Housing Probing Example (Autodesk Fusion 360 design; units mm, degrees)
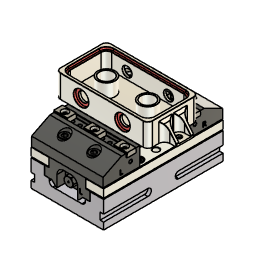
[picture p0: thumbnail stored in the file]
parameter "stockX" = 165.1 comment "Stock in X"
parameter "stockY" = 76.2 comment "Stock in Y"
parameter "stockZ" = 38.1 comment "Stock in Z"
as_built_joint "As-built1"
sketch "Sketch1" plane through (0, 0, 0) normal (0, 0, 1) x axis (1, 0, 0)
  line L1 (-63.5, 34.925) -> (63.5, 34.925)
  line L2 (-63.5, -34.925) -> (-63.5, 34.925)
  line L3 (63.5, -34.925) -> (-63.5, -34.925)
  line L4 (63.5, 34.925) -> (63.5, -34.925)
  line L5 (-63.5, -34.925) -> (63.5, 34.925)
  line L6 (63.5, -34.925) -> (-63.5, 34.925)
  point P6 (0, 0)
  point P1 (0, 0)
  point P2 (63.5, 34.925)
  point P5 (63.5, -34.925)
  point P3 (-63.5, 34.925)
  perpendicular L1 L2
  parallel L1 L3
  parallel L2 L4
  horizontal L1
  coincident L5 P6
  coincident L6 P6
  coincident P1 P6
  dimension "d1" distance P2 P5 = 69.85
  dimension "d2" distance P2 P3 = 127
extrude "Extrude1" new body sketch "Sketch1" profile of L1 L2 L3 L4 along normal blind 31.75
sketch "Sketch2" plane through (0, 0, 31.75) normal (0, 0, 1) x axis (-1, 0, 0)
  line L1 (-63.5, -34.925) -> (-63.5, 34.925)
  line L2 (63.5, -34.925) -> (-63.5, -34.925)
  line L3 (63.5, 34.925) -> (63.5, -34.925)
  line L4 (-63.5, 34.925) -> (63.5, 34.925)
  line L5 (-57.15, 28.575) -> (57.15, 28.575)
  line L6 (-57.15, -28.575) -> (-57.15, 28.575)
  line L7 (57.15, -28.575) -> (-57.15, -28.575)
  line L8 (57.15, 28.575) -> (57.15, -28.575)
  dimension "d5" = 6.35
extrude "Extrude2" cut sketch "Sketch2" profile of L8 L5 L6 L7 against normal blind 25.4 (magnitude of "-1.2500 in + 0.25 in")
fillet "Fillet1" radius 7.3025 (= "( 0.25 * 1.15 ) * 1 in")
sketch "Sketch3" plane through (0, 0, 6.35) normal (0, 0, 1) x axis (-1, 0, 0)
  line L1 (-57.15, -21.2725) -> (-57.15, 21.2725)
  line L2 (49.8475, -28.575) -> (-49.8475, -28.575)
  line L3 (57.15, 21.2725) -> (57.15, -21.2725)
  line L4 (-49.8475, 28.575) -> (49.8475, 28.575)
  line L5 (-57.15, 0) -> (57.15, 0)
  line L6 (-57.15, 21.2725) -> (-57.15, -21.2725)
  arc A1 centre (-49.8475, 21.2725) radius 7.3025 clockwise from (-57.15, 21.2725) to (-49.8475, 28.575)
  arc A2 centre (-49.8475, -21.2725) radius 7.3025 clockwise from (-49.8475, -28.575) to (-57.15, -21.2725)
  arc A3 centre (49.8475, -21.2725) radius 7.3025 clockwise from (57.15, -21.2725) to (49.8475, -28.575)
  arc A4 centre (49.8475, 21.2725) radius 7.3025 clockwise from (49.8475, 28.575) to (57.15, 21.2725)
  circle C1 centre (-28.575, 0) radius 9.525
  circle C2 centre (28.575, 0) radius 9.525
  circle C3 centre (28.575, 0) radius 12.065
  circle C4 centre (-28.575, 0) radius 12.065
  point P14 (57.15, 0)
  point P15 (-57.15, 0)
  point P16 (-28.575, 0)
  point P17 (28.575, 0)
  point P1 (0, 0)
  midpoint L3 P14
  midpoint L1 P15
  coincident L5 P16
  coincident L5 P17
  equal C1 C2
  dimension "d9" distance P1 L6 = 57.15
  dimension "d10" distance P1 P16 = 28.575 (= "2.2500 in / 2")
  dimension "d11" distance P1 P17 = 28.575 (= "d10")
  dimension "d12" diameter C1 = 19.05
  dimension "d13" = 2.54
  dimension "d14" = 2.54 (= "d13")
extrude "Extrude3" add sketch "Sketch3" profile of C1 C2 C4 C3 along normal blind 19.05 (= "1.0000 in - 0.25 in")
sketch "Sketch4" plane through (0, 0, 6.35) normal (0, 0, 1) x axis (-1, 0, 0)
  circle C1 centre (28.575, 0) radius 6.6675
  circle C2 centre (-28.575, 0) radius 6.6675
  circle C3 centre (-28.575, 0) radius 9.525
  circle C4 centre (28.575, 0) radius 9.525
  concentric C2 C3
  concentric C1 C4
  equal C1 C2
  dimension "d17" diameter C1 = 13.335
extrude "Extrude4" cut sketch "Sketch4" profile of C1 C2 no distance stored
sketch "Sketch5" plane through (0, 0, 0) normal (0, 0, -1) x axis (1, 0, 0)
  circle C1 centre (-28.575, 0) radius 10.16
  circle C2 centre (28.575, 0) radius 10.16
  circle C3 centre (28.575, 0) radius 6.6675
  circle C4 centre (-28.575, 0) radius 6.6675
  concentric C2 C3
  concentric C1 C4
  equal C1 C2
  dimension "d19" diameter C2 = 20.32
extrude "Extrude5" cut sketch "Sketch5" against normal blind 3.175 (magnitude of "-0.2500 in / 2")
fillet "Fillet2" radius 6.35
sketch "Sketch6" plane through (0, 0, 31.75) normal (0, 0, 1) x axis (-1, 0, 0)
  line L1 (-63.5, -28.575) -> (-63.5, 28.575)
  line L2 (57.15, -34.925) -> (-57.15, -34.925)
  line L3 (63.5, 28.575) -> (63.5, -28.575)
  line L4 (-57.15, 34.925) -> (57.15, 34.925)
  line L5 (49.8475, 28.575) -> (-49.8475, 28.575)
  line L6 (57.15, -21.2725) -> (57.15, 21.2725)
  line L7 (-49.8475, -28.575) -> (49.8475, -28.575)
  line L8 (-57.15, 21.2725) -> (-57.15, -21.2725)
  line L9 (-49.8475, -31.115) -> (49.8475, -31.115)
  line L10 (59.69, -21.2725) -> (59.69, 21.2725)
  line L11 (49.8475, 31.115) -> (-49.8475, 31.115)
  line L12 (-59.69, 21.2725) -> (-59.69, -21.2725)
  arc A1 centre (-57.15, 28.575) radius 6.35 clockwise from (-63.5, 28.575) to (-57.15, 34.925)
  arc A2 centre (-57.15, -28.575) radius 6.35 clockwise from (-57.15, -34.925) to (-63.5, -28.575)
  arc A3 centre (57.15, -28.575) radius 6.35 clockwise from (63.5, -28.575) to (57.15, -34.925)
  arc A4 centre (57.15, 28.575) radius 6.35 clockwise from (57.15, 34.925) to (63.5, 28.575)
  arc A5 centre (49.8475, 21.2725) radius 7.3025 clockwise from (49.8475, 28.575) to (57.15, 21.2725)
  arc A6 centre (49.8475, -21.2725) radius 7.3025 clockwise from (57.15, -21.2725) to (49.8475, -28.575)
  arc A7 centre (-49.8475, -21.2725) radius 7.3025 clockwise from (-49.8475, -28.575) to (-57.15, -21.2725)
  arc A8 centre (-49.8475, 21.2725) radius 7.3025 clockwise from (-57.15, 21.2725) to (-49.8475, 28.575)
  arc A9 centre (-49.8475, -21.2725) radius 9.8425 clockwise from (-49.8475, -31.115) to (-59.69, -21.2725)
  arc A10 centre (49.8475, -21.2725) radius 9.8425 clockwise from (59.69, -21.2725) to (49.8475, -31.115)
  arc A11 centre (49.8475, 21.2725) radius 9.8425 clockwise from (49.8475, 31.115) to (59.69, 21.2725)
  arc A12 centre (-49.8475, 21.2725) radius 9.8425 clockwise from (-59.69, 21.2725) to (-49.8475, 31.115)
  dimension "d23" = 2.54
extrude "Extrude6" cut sketch "Sketch6" profile of L5 A5 L6 A6 L7 A7 L8 A8 L12 A9 L9 A10 L10 A11 L11 A12 against normal blind 3.175
sketch "Sketch7" plane through (0, -34.925, 0) normal (0, -1, 0) x axis (1, 0, 0)
  line L1 (-40.64, 25.4) -> (-16.51, 25.4)
  line L2 (-16.51, 6.35) -> (-40.64, 6.35)
  line L3 (16.51, 25.4) -> (40.64, 25.4)
  line L4 (40.64, 6.35) -> (16.51, 6.35)
  line L5 (-28.575, 6.35) -> (-28.575, 25.4)
  line L6 (28.575, 6.35) -> (28.575, 25.4)
  circle C1 centre (-28.575, 15.875) radius 6.6675
  circle C2 centre (28.575, 15.875) radius 6.6675
  point P10 (-28.575, 25.4)
  point P11 (-28.575, 6.35)
  point P12 (28.575, 25.4)
  point P13 (28.575, 6.35)
  point P14 (-28.575, 15.875)
  point P15 (28.575, 15.875)
  midpoint L1 P10
  midpoint L2 P11
  midpoint L3 P12
  midpoint L4 P13
  midpoint L5 P14
  midpoint L6 P15
  equal C1 C2
  dimension "d26" diameter C2 = 13.335
extrude "Extrude7" cut sketch "Sketch7" profile of C1 C2 against normal blind 6.35
sketch "Sketch8" plane through (0, 34.925, 0) normal (0, 1, 0) x axis (-1, 0, 0)
  circle C1 centre (28.575, 15.875) radius 6.6675
  circle C2 centre (28.575, 15.875) radius 6.6675
  circle C3 centre (-28.575, 15.875) radius 6.6675
  circle C4 centre (-28.575, 15.875) radius 6.6675
extrude "Extrude8" cut sketch "Sketch8" against normal blind 6.35
sketch "Sketch9" plane through (0, -34.925, 0) normal (0, -1, 0) x axis (1, 0, 0)
  circle C1 centre (28.575, 15.875) radius 10.4775
  circle C2 centre (-28.575, 15.875) radius 10.4775
  circle C3 centre (28.575, 15.875) radius 6.6675
  circle C4 centre (-28.575, 15.875) radius 6.6675
  concentric C1 C3
  concentric C2 C4
  equal C1 C2
  dimension "d31" distance C1 C3 = 3.81
extrude "Extrude9" cut sketch "Sketch9" against normal blind 3.175 (magnitude of "-0.2500 in / 2")
sketch "Sketch10" plane through (0, 34.925, 0) normal (0, 1, 0) x axis (-1, 0, 0)
  circle C1 centre (28.575, 15.875) radius 6.6675
  circle C2 centre (28.575, 15.875) radius 10.4775
  circle C3 centre (-28.575, 15.875) radius 6.6675
  circle C4 centre (-28.575, 15.875) radius 10.4775
extrude "Extrude10" cut sketch "Sketch10" against normal blind 3.175 (magnitude of "-0.2500 in / 2")
sketch "Sketch1" plane through (0, 0, 28.575) normal (0, 0, 1) x axis (-1, 0, 0)
  line L1 (-49.8475, -31.115) -> (49.8475, -31.115)
  line L2 (-59.69, 21.2725) -> (-59.69, -21.2725)
  line L3 (49.8475, 31.115) -> (-49.8475, 31.115)
  line L4 (59.69, -21.2725) -> (59.69, 21.2725)
  line L5 (49.8475, 31.0896) -> (-49.8475, 31.0896)
  line L6 (-59.6646, 21.2725) -> (-59.6646, -21.2725)
  line L7 (-49.8475, -31.0896) -> (49.8475, -31.0896)
  line L8 (59.6646, -21.2725) -> (59.6646, 21.2725)
  arc A1 centre (49.8475, -21.2725) radius 9.8425 clockwise from (59.69, -21.2725) to (49.8475, -31.115)
  arc A2 centre (-49.8475, -21.2725) radius 9.8425 clockwise from (-49.8475, -31.115) to (-59.69, -21.2725)
  arc A3 centre (-49.8475, 21.2725) radius 9.8425 clockwise from (-59.69, 21.2725) to (-49.8475, 31.115)
  arc A4 centre (49.8475, 21.2725) radius 9.8425 clockwise from (49.8475, 31.115) to (59.69, 21.2725)
  arc A5 centre (49.8475, 21.2725) radius 9.8171 clockwise from (49.8475, 31.0896) to (59.6646, 21.2725)
  arc A6 centre (-49.8475, 21.2725) radius 9.8171 clockwise from (-59.6646, 21.2725) to (-49.8475, 31.0896)
  arc A7 centre (-49.8475, -21.2725) radius 9.8171 clockwise from (-49.8475, -31.0896) to (-59.6646, -21.2725)
  arc A8 centre (49.8475, -21.2725) radius 9.8171 clockwise from (59.6646, -21.2725) to (49.8475, -31.0896)
  dimension "d36" = 0.0254
extrude "Extrude1" new body sketch "Sketch1" profile of L8 A6 L5 A5 L6 A7 A8 L7 along normal blind 3.175
as_built_joint "As-built2"
sketch "Sketch1" plane through (0, 34.925, 0) normal (0, 1, 0) x axis (-1, 0, 0)
  circle C1 centre (-28.575, 15.875) radius 10.4775
  circle C2 centre (-28.575, 15.875) radius 10.4521
  dimension "d39" = 0.0254
extrude "Extrude1" new body sketch "Sketch1" profile of C2 against normal blind 3.175
sketch "Sketch2" plane through (0, 31.75, 0) normal (0, -1, 0) x axis (1, 0, 0)
  circle C1 centre (28.575, 15.875) radius 6.6675
  circle C2 centre (28.575, 15.875) radius 6.6421
  dimension "d42" = 0.0254 (= "1.000E-03 in")
extrude "Extrude2" add sketch "Sketch2" profile of C2 along normal blind 6.35
sketch "Sketch3" plane through (0, 25.4, 0) normal (0, -1, 0) x axis (1, 0, 0)
  circle C1 centre (28.575, 15.875) radius 3.175
  circle C2 centre (28.575, 15.875) radius 6.6675
  concentric C1 C2
  dimension "d45" diameter C1 = 6.35
extrude "Extrude3" add sketch "Sketch3" profile of C1 along normal blind 6.35
sketch "Sketch4" plane through (0, 19.05, 0) normal (0, -1, 0) x axis (1, 0, 0)
  circle C1 centre (28.575, 15.875) radius 0.8001
  circle C2 centre (28.575, 15.875) radius 3.175
  concentric C1 C2
  dimension "d48" diameter C1 = 1.6002
extrude "Extrude4" add sketch "Sketch4" profile of C1 along normal blind 5.08
sketch "Sketch5" plane through (0, 34.925, 0) normal (0, 1, 0) x axis (-1, 0, 0)
  circle C1 centre (-28.575, 15.875) radius 6.35
  circle C2 centre (-28.575, 15.875) radius 10.4521
  concentric C1 C2
  dimension "d51" diameter C1 = 12.7
extrude "Extrude5" add sketch "Sketch5" profile of C1 along normal blind 0.762
sketch "Sketch6" plane through (0, 35.687, 0) normal (0, 1, 0) x axis (-1, 0, 0)
  line L1 (-33.1577, 23.8125) -> (-23.9923, 23.8125)
  line L2 (-37.7404, 15.875) -> (-33.1577, 23.8125)
  line L3 (-33.1577, 7.9375) -> (-37.7404, 15.875)
  line L4 (-23.9923, 7.9375) -> (-33.1577, 7.9375)
  line L5 (-19.4096, 15.875) -> (-23.9923, 7.9375)
  line L6 (-23.9923, 23.8125) -> (-19.4096, 15.875)
  line L7 (-49.8475, 28.575) -> (49.8475, 28.575)
  circle C1 centre (-28.575, 15.875) radius 6.35
  point P2 (-28.575, 15.875)
  point P9 (-28.575, 15.875)
  coincident P2 P9
  parallel L1 L7
  dimension "d54" distance L1 L4 = 15.875
extrude "Extrude6" add sketch "Sketch6" profile of L1 L2 L3 L4 L5 L6 along normal blind 8.89
fillet "Fillet1" radius 0.762
sketch "Sketch8" plane through (0, 44.577, 0) normal (0, 1, 0) x axis (-1, 0, 0)
  circle C1 centre (-28.575, 15.875) radius 6.985
  circle C2 centre (-28.575, 15.875) radius 10.4521
  concentric C1 C2
  dimension "d59" diameter C1 = 13.97
extrude "Extrude7" add sketch "Sketch8" profile of C1 along normal blind 3.175
work_plane "WorkPlane1"
sketch "Sketch9" plane through (28.575, 43.307, 15.875) normal (0.866, 0, 0.5) x axis (0.5, 0, -0.866)
  line L1 (-6.35, -7.62) -> (6.35, -7.62)
  line L2 (6.35, -8.382) -> (-6.35, -8.382)
  line L3 (-6.985, 4.445) -> (6.985, 4.445)
  line L4 (6.985, 1.27) -> (-6.985, 1.27)
  line L5 (-4.8027, 1.27) -> (-4.8027, -7.62)
  line L6 (-8.9455, 1.27) -> (-4.8027, 1.27)
  line L7 (-8.9455, -7.62) -> (-8.9455, 1.27)
  line L8 (-4.8027, -7.62) -> (-8.9455, -7.62)
  line L9 (-8.9455, 1.27) -> (-9.0476, 1.27)
  line L10 (-8.9455, -7.62) -> (-8.9455, 1.27)
  line L11 (-9.0476, -7.62) -> (-8.9455, -7.62)
  line L12 (-8.9455, 1.27) -> (-8.9455, -7.62)
  line L13 (-9.0476, 1.27) -> (-9.0476, -7.62)
  line L14 (-9.0476, 1.27) -> (-6.985, 1.27)
  line L15 (-9.0476, 1.27) -> (-9.0476, 0)
  line L16 (-9.0476, -7.62) -> (-9.0476, -6.35)
  line L17 (-6.35, -7.62) -> (-9.0476, -7.62)
  arc A1 centre (-6.985, -1.0399) radius 2.3099 clockwise from (-9.0476, 0) to (-6.985, 1.27)
  arc A2 centre (-6.35, -4.1201) radius 3.4999 clockwise from (-6.35, -7.62) to (-9.0476, -6.35)
  point P17 (-9.0476, -7.62)
  point P18 (-9.0476, -7.62)
  point P14 (-9.0476, 1.27)
  point P19 (-9.0476, 1.27)
  point P21 (-9.0476, 0)
  point P24 (-9.0476, -6.35)
  point P26 (-9.0476, -7.62)
  point P8 (-6.985, 1.27)
  point P20 (-6.985, 1.27)
  point P3 (-6.35, -7.62)
  point P23 (-6.35, -7.62)
  point P12 (-8.9455, 1.27)
  coincident P17 P18
  coincident P14 P19
  coincident L13 P21
  tangent L4 A1
  coincident L13 P24
  tangent L1 A2
  tangent A1 L14
  perpendicular L14 L15
  coincident P17 P26
  tangent A2 L17
  coincident P8 P20
  coincident P3 P23
  dimension "d62" distance P12 P21 = 1.27
  dimension "d63" distance P17 P24 = 1.27 (= "d62")
work_axis "WorkAxis1"
revolve "Revolve1" sketch "Sketch9" AlongAngle 360
sketch "Sketch10" plane through (0, 47.752, 0) normal (0, 1, 0) x axis (-1, 0, 0)
  circle C1 centre (-28.575, 15.875) radius 6.223
  circle C2 centre (-28.575, 15.875) radius 6.985
  concentric C1 C2
  dimension "d65" distance C1 C2 = 0.762
extrude "Extrude8" cut sketch "Sketch10" profile of C1 against normal blind 2.54
sketch "Sketch11" plane through (0, 45.212, 0) normal (0, 1, 0) x axis (-1, 0, 0)
  circle C1 centre (-28.575, 15.875) radius 1.5875
  circle C2 centre (-28.575, 15.875) radius 1.2065
  circle C3 centre (-28.575, 15.875) radius 6.223
  concentric C1 C2
  concentric C1 C3
  dimension "d68" distance C1 C2 = 0.381
  dimension "d69" diameter C1 = 3.175
extrude "Extrude9" add sketch "Sketch11" profile of C1 C2 along normal blind 1.016
extrude "Extrude10" cut of existing geometry blind -2.54
as_built_joint "As-built3"
copy_paste "CutPaste"
copy_paste "CopyPaste2"
copy_paste "CopyPaste3"
copy_paste "CopyPaste4"
copy_paste "CopyPaste5"
copy_paste "CopyPaste6"
joint "Assemble1" alignAngle 180 alignOffsetX 0 alignOffsetY 0 alignOffsetZ 0
joint "Assemble2" sketch "Sketch2" alignAngle 180 alignOffsetX 0 alignOffsetY 0 alignOffsetZ 0
joint "Assemble3" sketch "Sketch2" alignAngle 0 alignOffsetX 0 alignOffsetY 0 alignOffsetZ 0
joint "Assemble4" sketch "Sketch2" alignAngle 180 alignOffsetX 0 alignOffsetY 0 alignOffsetZ 0
joint "Assemble5" sketch "Sketch2" alignAngle 180 alignOffsetX 0 alignOffsetY 0 alignOffsetZ 0
sketch "Sketch11" plane through (0, 0, 0) normal (0, 1, 0) x axis (1, 0, 0)
  line L1 (-63.5, 0) -> (-63.5, -31.75)
  line L2 (-80.01, 0) -> (-63.5, 0)
  line L3 (-80.01, -3.81) -> (-80.01, 0)
  line L4 (-63.5, -23.8125) -> (-80.01, -3.81)
  point P3 (-63.5, 0)
  point P4 (-63.5, 0)
  point P7 (-63.5, -23.8125)
  point P2 (-63.5, -31.75)
  point P8 (-63.5, 0)
  point P5 (-80.01, 0)
  point P6 (-80.01, -3.81)
  coincident P3 P4
  perpendicular L1 L2
  perpendicular L2 L3
  coincident L1 P7
  dimension "d134" distance P2 P3 = 31.75
  dimension "d135" distance P7 P8 = 23.8125 (= "1.2500 in * 0.75")
  dimension "d136" distance P5 P6 = 3.81
  dimension "d137" distance P4 P5 = 16.51
extrude "Extrude11" add sketch "Sketch11" distance 24.13 (= "0.65 in + 0.3 in")
sketch "Sketch12" plane through (0, 0, 31.75) normal (0, 0, 1) x axis (-1, 0, 0)
  line L1 (63.5, -12.065) -> (63.5, 12.065)
  line L2 (80.01, -12.065) -> (63.5, -12.065)
  line L3 (80.01, 12.065) -> (80.01, -12.065)
  line L4 (63.5, 12.065) -> (80.01, 12.065)
  line L5 (63.5, 0) -> (80.01, 0)
  line L6 (63.5, -8.255) -> (80.01, -8.255)
  line L7 (63.5, 8.255) -> (63.5, -8.255)
  line L8 (80.01, 8.255) -> (63.5, 8.255)
  line L9 (80.01, -8.255) -> (80.01, 8.255)
  circle C1 centre (71.755, 0) radius 3.2639
  circle C2 centre (71.755, 0) radius 7.9375
  point P6 (80.01, 0)
  point P7 (63.5, 0)
  point P8 (71.755, 0)
  point P11 (63.5, 8.255)
  point P9 (80.01, -8.255)
  midpoint L3 P6
  midpoint L1 P7
  midpoint L5 P8
  horizontal L6
  vertical L7
  horizontal L8
  vertical L9
  coincident L1 P11
  coincident L3 P9
  concentric C1 C2
  dimension "d140" diameter C1 = 6.5278
  dimension "d141" distance L2 L6 = 3.81
  dimension "d142" distance L4 L8 = 3.81 (= "d141")
  dimension "d146" diameter C2 = 15.875
extrude "Extrude12" cut sketch "Sketch12" profile of C1 L6 L7 L8 L9 against normal blind 29.21 (magnitude of "-1.1000 in - 0.05 in")
extrude "Extrude13" cut sketch "Sketch12" profile of C1 no distance stored
fillet "Fillet3" radius 7.62 (= "( 0.25 * 1.2 ) * 1 in")
fillet "Fillet4" radius 0.762
chamfer "Chamfer1" distance 0.254
mirror "Mirror1"
base_feature "Base Feature1" OffsetX 0 OffsetY 0 OffsetZ 0 AngleZ 0
base_feature "Base Feature1"
base_feature "Base Feature1"
base_feature "Base Feature1"
base_feature "Base Feature1"
base_feature "Base Feature1"
base_feature "Base Feature1"
base_feature "Base Feature1"
base_feature "Base Feature1" OffsetX 0 named "d129_1" OffsetY 0 named "d130_1" OffsetZ 0 named "d131_1" AngleZ 0 named "d132_1" OffsetX 0 named "d141_1" OffsetY 0 named "d142_1" OffsetZ 0 named "d143_1" AngleZ 0 named "d144_1" OffsetX 0 named "d149_1" OffsetY 0 named "d150_1" OffsetZ 0 named "d151_1" AngleZ 0 OffsetX 0 OffsetY 0 OffsetZ 0 AngleZ 0 OffsetX 0 OffsetY 0 OffsetZ 0 AngleZ 0
base_feature "Base Feature1" OffsetX 0 named "d125_1" OffsetY 0 named "d126_1" OffsetZ 0 named "d127_1" AngleZ 0 named "d128_1" OffsetX 0 named "d137_1" OffsetY 0 named "d138_1" OffsetZ 0 named "d139_1" AngleZ 0 named "d140_1" OffsetX 0 named "d145_1" OffsetY 0 named "d146_1" OffsetZ 0 AngleZ 0 named "d148_1" OffsetX 0 OffsetY 0 OffsetZ 0 AngleZ 0 OffsetX 0 OffsetY 0 OffsetZ 0 AngleZ 0
base_feature "Base Feature1"
base_feature "Base Feature1" OffsetX 0 OffsetY 0 OffsetZ 0 AngleZ 0
base_feature "Base Feature1"
base_feature "Base Feature1"
as_built_joint "As-built2"
as_built_joint "As-built2"
as_built_joint "As-built2"
as_built_joint "As-built2"
as_built_joint "As-built2"
as_built_joint "As-built14" OffsetX 0 OffsetY 0 OffsetZ 0 AngleZ 0
as_built_joint "As-built15"
as_built_joint "As-built16"
joint_origin "JointOrigin5" OffsetX 0 OffsetY 0 OffsetZ 75.4629 AngleZ 0
sketch "Sketch1" plane through (0, 0, 0) normal (0, 1, 0) x axis (1, 0, 0)
  line L1 (82.55, -38.1) -> (-82.55, -38.1)
  line L2 (82.55, 38.1) -> (82.55, -38.1)
  line L3 (-82.55, 38.1) -> (82.55, 38.1)
  line L4 (-82.55, -38.1) -> (-82.55, 38.1)
  line L5 (82.55, 38.1) -> (-82.55, -38.1)
  line L6 (-82.55, 38.1) -> (82.55, -38.1)
  point P6 (0, 0)
  point P1 (0, 0)
  point P2 (-82.55, -38.1)
  point P3 (82.55, -38.1)
  point P5 (-82.55, 38.1)
  perpendicular L1 L2
  parallel L1 L3
  parallel L2 L4
  horizontal L1
  coincident L5 P6
  coincident L6 P6
  coincident P1 P6
  dimension "d475" distance P2 P3 = 165.1 (= "stockX")
  dimension "d476" distance P2 P5 = 76.2 (= "stockY")
extrude "Extrude1" new body sketch "Sketch1" profile of L1 L2 L3 L4 along normal blind 38.1 (= "stockZ")
joint "Assemble21" alignAngle 0 alignOffsetX 0 alignOffsetY 0 alignOffsetZ 0
ground "Ground2"
joint_origin "JointOrigin1" OffsetX 0 OffsetY 0.762 OffsetZ 0 AngleZ 0
joint "Assemble22" alignAngle 0 alignOffsetX 0.0559 (= "-1.2478 in + ( stockY / 2 ) - 0.25 in") alignOffsetY 0 alignOffsetZ 0
joint "Assemble23" alignAngle 0 alignOffsetX 0.0559 (= "-1.2478 in + ( stockY / 2 ) - 0.25 in") alignOffsetY 0 alignOffsetZ 0
base_feature "Base Feature1"
joint "Assemble24" sketch "Sketch2" OffsetX 0 OffsetY 0 OffsetZ 0 AngleZ 0 alignAngle -90 alignOffsetX 0 alignOffsetY 0 alignOffsetZ 0
rectangular_pattern "00000000-0000-0000-0000-000000000000" uSpaceDistance -41.2496 vSpaceDistance 0
as_built_joint "As-built20"
as_built_joint "As-built21"
copy_paste "CopyPaste1"
joint "Assemble25" sketch "Sketch2" alignAngle 90 alignOffsetX 0 alignOffsetY 0 alignOffsetZ 0
rectangular_pattern "00000000-0000-0000-0000-000000000000" uSpaceDistance 41.2496 vSpaceDistance 0
as_built_joint "As-built22"
as_built_joint "As-built23"
ground "Ground3"
position "Position1"
joint "Assemble7" sketch "Sketch2" alignAngle 0 alignOffsetX 0 alignOffsetY 0 alignOffsetZ -3.175
joint_origin "JointOrigin6" OffsetX 0 OffsetY 0 OffsetZ -75.4126 AngleZ 0
chamfer "Chamfer2" distance 0.254
joint_origin "JointOrigin8" OffsetX 0 OffsetY 0.254 OffsetZ 6.35 AngleZ 0
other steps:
create_component "CreateComponent1"
create_component "CreateComponent2"
create_component "CreateComponent3"
create_component "CreateComponent4"
remove_instance "RemoveInstance1"
joint_origin "JointOrigin1" OffsetX 0 OffsetY 0 OffsetZ 0 AngleZ 0
joint_origin "JointOrigin1" OffsetX 0 OffsetY 0 OffsetZ 0 AngleZ 0
joint_origin "JointOrigin2" OffsetX 0 OffsetY 0 OffsetZ 0 AngleZ 0
joint_origin "JointOrigin2" OffsetX 0 OffsetY 0 OffsetZ 0 AngleZ 0
joint_origin "JointOrigin3" OffsetX 0 OffsetY 0 OffsetZ 0 AngleZ 0
joint_origin "JointOrigin3" OffsetX 0 OffsetY 0 OffsetZ 0 AngleZ 0
joint_origin "JointOrigin4" OffsetX 0 OffsetY 0 OffsetZ 0 AngleZ 0
joint_origin "JointOrigin4" OffsetX 0 OffsetY 0 OffsetZ 0 AngleZ 0
joint_origin "JointOrigin5" OffsetX 0 OffsetY 0 OffsetZ 0 AngleZ 0
joint_origin "JointOrigin5" OffsetX 0 OffsetY 0 OffsetZ 0 AngleZ 0
create_component "CreateComponent1"
create_component "CreateComponent1"
create_component "CreateComponent2"
create_component "CreateComponent3"
create_component "CreateComponent4"
create_component "CreateComponent5"
create_component "CreateComponent6"
create_component "CreateComponent7"
create_component "CreateComponent2"
create_component "CreateComponent1"
create_component "CreateComponent2"
create_component "CreateComponent3"
create_component "CreateComponent1"
create_component "CreateComponent4"
create_component "CreateComponent1"
create_component "CreateComponent2"
create_component "CreateComponent5"
create_component "CreateComponent1"
create_component "CreateComponent6"
create_component "CreateComponent30"
joint_origin "JointOrigin1" OffsetX 0 OffsetY 0 OffsetZ 0 AngleZ 0
joint_origin "JointOrigin1" OffsetX 0 OffsetY 0 OffsetZ 0 AngleZ 0
joint_origin "JointOrigin2" OffsetX 0 OffsetY 0 OffsetZ 0 AngleZ 0
create_component "CreateComponent31"
joint_origin "JointOrigin11" OffsetX 0 OffsetY 0 OffsetZ 0 AngleZ 0
create_component "CreateComponent1"
joint_origin "JointOrigin1" OffsetX 0 OffsetY 0 OffsetZ 0 AngleZ 0
joint_origin "JointOrigin11" OffsetX 0 OffsetY 0 OffsetZ 0 AngleZ 0
create_component "CreateComponent5"
joint_origin "JointOrigin7" OffsetX 0 OffsetY 0 OffsetZ 0 AngleZ 0
joint_origin "JointOrigin3" OffsetX 0 OffsetY 0 OffsetZ 0 AngleZ 0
